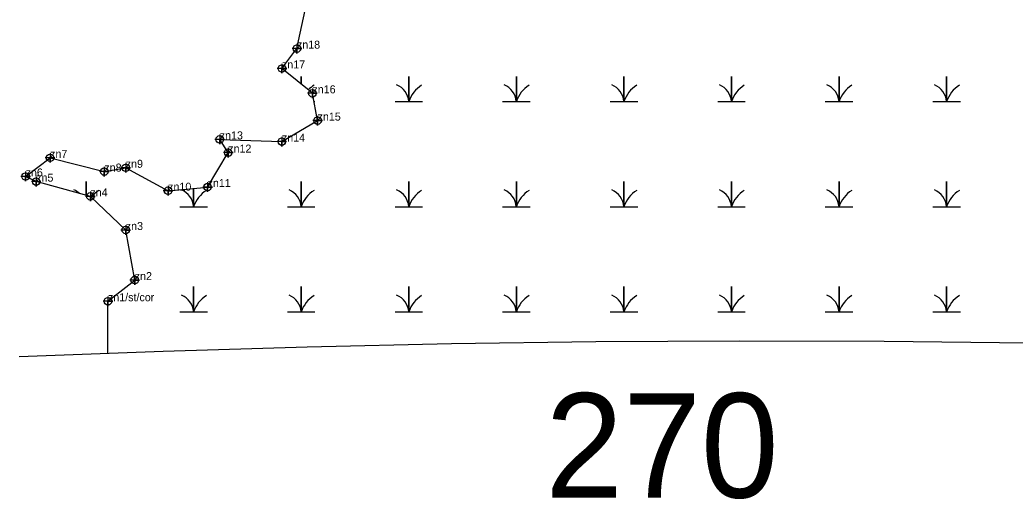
# Model space of a CAD drawing. Extents: x 2071991 to 2268989, y 436479 to 469629.
# Drawn here: x 2230233 to 2230854, y 437821 to 438121 of the extents above; entities that cross this region are included whole.
import ezdxf

# ---------------------------------------------------------------- set-up
doc = ezdxf.new("R2010")
doc.units = 0
for name, color, linetype in [('approx_PSA', 7, 'Continuous'), ('Default', 7, 'Continuous'), ('Exist Environmental Wetland Boundary', 7, 'Continuous'), ('Exist Environmental Wetland Boundary Cogo Comment', 7, 'Continuous'), ('Exist Environmental Wetland Boundary Cogo Point CELL', 7, 'Continuous'), ('Exist Hydro Swamp or Marsh', 7, 'Continuous')]:
    doc.layers.add(name, color=color, linetype=linetype)

msp = doc.modelspace()

# ---------------------------------------------------------------- linework, layer by layer
at = {"layer": 'approx_PSA'}
for p, q in [((2230412.08, 437916.61), (2230322, 437913.9)), ((2230502.18, 437918.58), (2230412.08, 437916.61)), ((2230592.29, 437919.8), (2230502.18, 437918.58)), ((2230682.41, 437920.29), (2230592.29, 437919.8)), ((2230772.53, 437920.03), (2230682.41, 437920.29)), ((2230862.64, 437919.04), (2230772.53, 437920.03)), ((2230322, 437913.9), (2230231.95, 437910.45))]:
    msp.add_line(p, q, dxfattribs=at)
at = {"layer": 'Exist Environmental Wetland Boundary'}
msp.add_lwpolyline([(2230287.44, 437912.58), (2230287.5, 437945.27), (2230304.22, 437958.48), (2230298.64, 437989.83), (2230276.54, 438010.89), (2230242.65, 438020.09), (2230236.05, 438023.33), (2230251.36, 438034.96), (2230285.25, 438026.39), (2230298.62, 438028.75), (2230325.1, 438014.42), (2230349.74, 438016.73), (2230362.65, 438038.26), (2230357.36, 438046.53), (2230396.17, 438045.12), (2230418.47, 438058.27), (2230415.26, 438075.34), (2230396.2, 438090.88), (2230405.57, 438103.3), (2230411.69, 438132.22)], dxfattribs=at)
at = {"layer": 'Exist Environmental Wetland Boundary Cogo Point CELL'}
for points in [[(2230405.57, 438106.3), (2230405.57, 438100.3), (2230405.57, 438103.3), (2230408.57, 438103.3), (2230402.57, 438103.3)], [(2230396.2, 438093.88), (2230396.2, 438087.88), (2230396.2, 438090.88), (2230399.2, 438090.88), (2230393.2, 438090.88)], [(2230415.26, 438078.34), (2230415.26, 438072.34), (2230415.26, 438075.34), (2230418.26, 438075.34), (2230412.26, 438075.34)], [(2230418.47, 438061.27), (2230418.47, 438055.27), (2230418.47, 438058.27), (2230421.47, 438058.27), (2230415.47, 438058.27)], [(2230357.36, 438049.53), (2230357.36, 438043.53), (2230357.36, 438046.53), (2230360.36, 438046.53), (2230354.36, 438046.53)], [(2230396.17, 438048.12), (2230396.17, 438042.12), (2230396.17, 438045.12), (2230399.17, 438045.12), (2230393.17, 438045.12)], [(2230362.65, 438041.26), (2230362.65, 438035.26), (2230362.65, 438038.26), (2230365.65, 438038.26), (2230359.65, 438038.26)], [(2230251.36, 438037.96), (2230251.36, 438031.96), (2230251.36, 438034.96), (2230254.36, 438034.96), (2230248.36, 438034.96)], [(2230285.25, 438029.39), (2230285.25, 438023.39), (2230285.25, 438026.39), (2230288.25, 438026.39), (2230282.25, 438026.39)], [(2230298.62, 438031.75), (2230298.62, 438025.75), (2230298.62, 438028.75), (2230301.62, 438028.75), (2230295.62, 438028.75)], [(2230236.05, 438026.33), (2230236.05, 438020.33), (2230236.05, 438023.33), (2230239.05, 438023.33), (2230233.05, 438023.33)], [(2230242.65, 438023.09), (2230242.65, 438017.09), (2230242.65, 438020.09), (2230245.65, 438020.09), (2230239.65, 438020.09)], [(2230325.1, 438017.42), (2230325.1, 438011.42), (2230325.1, 438014.42), (2230328.1, 438014.42), (2230322.1, 438014.42)], [(2230349.74, 438019.73), (2230349.74, 438013.73), (2230349.74, 438016.73), (2230352.74, 438016.73), (2230346.74, 438016.73)], [(2230276.54, 438013.89), (2230276.54, 438007.89), (2230276.54, 438010.89), (2230279.54, 438010.89), (2230273.54, 438010.89)], [(2230298.64, 437992.83), (2230298.64, 437986.83), (2230298.64, 437989.83), (2230301.64, 437989.83), (2230295.64, 437989.83)], [(2230304.22, 437961.48), (2230304.22, 437955.48), (2230304.22, 437958.48), (2230307.22, 437958.48), (2230301.22, 437958.48)], [(2230287.5, 437948.27), (2230287.5, 437942.27), (2230287.5, 437945.27), (2230290.5, 437945.27), (2230284.5, 437945.27)]]:
    msp.add_lwpolyline(points, dxfattribs=at)
for centre in [(2230405.57, 438103.3), (2230396.2, 438090.88), (2230415.26, 438075.34), (2230418.47, 438058.27), (2230357.36, 438046.53), (2230396.17, 438045.12), (2230251.36, 438034.96), (2230362.65, 438038.26), (2230285.25, 438026.39), (2230298.62, 438028.75), (2230236.05, 438023.33), (2230242.65, 438020.09), (2230325.1, 438014.42), (2230349.74, 438016.73), (2230276.54, 438010.89), (2230298.64, 437989.83), (2230304.22, 437958.48), (2230287.5, 437945.27)]:
    msp.add_circle(centre, 2.34, dxfattribs=at)
at = {"layer": 'Exist Hydro Swamp or Marsh'}
msp.add_line((2230416.23, 438070.18), (2230416.87, 438070.18), dxfattribs=at)
for points in [[(2230408.26, 438081.04), (2230408.26, 438085.96), (2230408.26, 438081.04)], [(2230466.87, 438070.18), (2230475.47, 438070.18), (2230475.47, 438085.96), (2230475.47, 438070.18), (2230484.07, 438070.18)], [(2230534.07, 438070.18), (2230542.67, 438070.18), (2230542.67, 438085.96), (2230542.67, 438070.18), (2230551.27, 438070.18)], [(2230601.27, 438070.18), (2230609.87, 438070.18), (2230609.87, 438085.96), (2230609.87, 438070.18), (2230618.48, 438070.18)], [(2230668.48, 438070.18), (2230677.08, 438070.18), (2230677.08, 438085.96), (2230677.08, 438070.18), (2230685.68, 438070.18)], [(2230735.68, 438070.18), (2230744.28, 438070.18), (2230744.28, 438085.96), (2230744.28, 438070.18), (2230752.88, 438070.18)], [(2230802.88, 438070.18), (2230811.48, 438070.18), (2230811.48, 438085.96), (2230811.48, 438070.18), (2230820.09, 438070.18)], [(2230273.86, 438011.62), (2230273.86, 438020.18), (2230273.86, 438011.62)], [(2230399.66, 438004.4), (2230408.26, 438004.4), (2230408.26, 438020.18), (2230408.26, 438004.4), (2230416.87, 438004.4)], [(2230466.87, 438004.4), (2230475.47, 438004.4), (2230475.47, 438020.18), (2230475.47, 438004.4), (2230484.07, 438004.4)], [(2230534.07, 438004.4), (2230542.67, 438004.4), (2230542.67, 438020.18), (2230542.67, 438004.4), (2230551.27, 438004.4)], [(2230601.27, 438004.4), (2230609.87, 438004.4), (2230609.87, 438020.18), (2230609.87, 438004.4), (2230618.48, 438004.4)], [(2230668.48, 438004.4), (2230677.08, 438004.4), (2230677.08, 438020.18), (2230677.08, 438004.4), (2230685.68, 438004.4)], [(2230735.68, 438004.4), (2230744.28, 438004.4), (2230744.28, 438020.18), (2230744.28, 438004.4), (2230752.88, 438004.4)], [(2230802.88, 438004.4), (2230811.48, 438004.4), (2230811.48, 438020.18), (2230811.48, 438004.4), (2230820.09, 438004.4)], [(2230332.46, 438004.4), (2230341.06, 438004.4), (2230341.06, 438015.92)], [(2230341.06, 438015.92), (2230341.06, 438004.4), (2230349.66, 438004.4)], [(2230332.46, 437938.62), (2230341.06, 437938.62), (2230341.06, 437954.4), (2230341.06, 437938.62), (2230349.66, 437938.62)], [(2230399.66, 437938.62), (2230408.26, 437938.62), (2230408.26, 437954.4), (2230408.26, 437938.62), (2230416.87, 437938.62)], [(2230466.87, 437938.62), (2230475.47, 437938.62), (2230475.47, 437954.4), (2230475.47, 437938.62), (2230484.07, 437938.62)], [(2230534.07, 437938.62), (2230542.67, 437938.62), (2230542.67, 437954.4), (2230542.67, 437938.62), (2230551.27, 437938.62)], [(2230601.27, 437938.62), (2230609.87, 437938.62), (2230609.87, 437954.4), (2230609.87, 437938.62), (2230618.48, 437938.62)], [(2230668.48, 437938.62), (2230677.08, 437938.62), (2230677.08, 437954.4), (2230677.08, 437938.62), (2230685.68, 437938.62)], [(2230735.68, 437938.62), (2230744.28, 437938.62), (2230744.28, 437954.4), (2230744.28, 437938.62), (2230752.88, 437938.62)], [(2230802.88, 437938.62), (2230811.48, 437938.62), (2230811.48, 437954.4), (2230811.48, 437938.62), (2230820.09, 437938.62)]]:
    msp.add_lwpolyline(points, dxfattribs=at)
for centre, radius, start, end in [((2230426.51, 438064.12), 19.22, 122.12745, 136.07469), ((2230463.2, 438069.29), 12.3, 4.14034, 67.53497), ((2230493.71, 438064.12), 19.22, 122.12745, 161.62219), ((2230530.4, 438069.29), 12.3, 4.14034, 67.53497), ((2230560.91, 438064.12), 19.22, 122.12745, 161.62219), ((2230597.61, 438069.29), 12.3, 4.14034, 67.53497), ((2230628.12, 438064.12), 19.22, 122.12745, 161.62219), ((2230664.81, 438069.29), 12.3, 4.14034, 67.53497), ((2230695.32, 438064.12), 19.22, 122.12745, 161.62219), ((2230732.01, 438069.29), 12.3, 4.14034, 67.53497), ((2230762.52, 438064.12), 19.22, 122.12745, 161.62219), ((2230799.22, 438069.29), 12.3, 4.14034, 67.53497), ((2230829.73, 438064.12), 19.22, 122.12745, 161.62219), ((2230261.59, 438003.51), 12.3, 48.65923, 67.53497), ((2230292.1, 437998.34), 19.22, 122.12745, 141.2888), ((2230328.8, 438003.51), 12.3, 4.14034, 67.53497), ((2230359.3, 437998.34), 19.22, 122.12745, 161.62219), ((2230396, 438003.51), 12.3, 4.14034, 67.53497), ((2230426.51, 437998.34), 19.22, 122.12745, 161.62219), ((2230463.2, 438003.51), 12.3, 4.14034, 67.53497), ((2230493.71, 437998.34), 19.22, 122.12745, 161.62219), ((2230530.4, 438003.51), 12.3, 4.14034, 67.53497), ((2230560.91, 437998.34), 19.22, 122.12745, 161.62219), ((2230597.61, 438003.51), 12.3, 4.14034, 67.53497), ((2230628.12, 437998.34), 19.22, 122.12745, 161.62219), ((2230664.81, 438003.51), 12.3, 4.14034, 67.53497), ((2230695.32, 437998.34), 19.22, 122.12745, 161.62219), ((2230732.01, 438003.51), 12.3, 4.14034, 67.53497), ((2230762.52, 437998.34), 19.22, 122.12745, 161.62219), ((2230799.22, 438003.51), 12.3, 4.14034, 67.53497), ((2230829.73, 437998.34), 19.22, 122.12745, 161.62219), ((2230328.8, 437937.73), 12.3, 4.14034, 67.53497), ((2230359.3, 437932.56), 19.22, 122.12745, 161.62219), ((2230396, 437937.73), 12.3, 4.14034, 67.53497), ((2230426.51, 437932.56), 19.22, 122.12745, 161.62219), ((2230463.2, 437937.73), 12.3, 4.14034, 67.53497), ((2230493.71, 437932.56), 19.22, 122.12745, 161.62219), ((2230530.4, 437937.73), 12.3, 4.14034, 67.53497), ((2230560.91, 437932.56), 19.22, 122.12745, 161.62219), ((2230597.61, 437937.73), 12.3, 4.14034, 67.53497), ((2230628.12, 437932.56), 19.22, 122.12745, 161.62219), ((2230664.81, 437937.73), 12.3, 4.14034, 67.53497), ((2230695.32, 437932.56), 19.22, 122.12745, 161.62219), ((2230732.01, 437937.73), 12.3, 4.14034, 67.53497), ((2230762.52, 437932.56), 19.22, 122.12745, 161.62219), ((2230799.22, 437937.73), 12.3, 4.14034, 67.53497), ((2230829.73, 437932.56), 19.22, 122.12745, 161.62219)]:
    msp.add_arc(centre, radius, start, end, dxfattribs=at)

# ---------------------------------------------------------------- texts
at = {"layer": 'Default'}
msp.add_text('270', height=65.34, dxfattribs=at).set_placement((2230560.8, 437822.39))
at = {"layer": 'Exist Environmental Wetland Boundary Cogo Comment'}
for s, p in [('zn18', (2230405.57, 438103.3)), ('zn17', (2230396.2, 438090.88)), ('zn16', (2230415.26, 438075.34)), ('zn15', (2230418.47, 438058.27)), ('zn13', (2230357.36, 438046.53)), ('zn14', (2230396.17, 438045.12)), ('zn12', (2230362.65, 438038.26)), ('zn7', (2230251.36, 438034.96)), ('zn8', (2230285.25, 438026.39)), ('zn9', (2230298.62, 438028.75)), ('zn6', (2230236.05, 438023.33)), ('zn5', (2230242.65, 438020.09)), ('zn10', (2230325.1, 438014.42)), ('zn11', (2230349.74, 438016.73)), ('zn4', (2230276.54, 438010.89)), ('zn3', (2230298.64, 437989.83)), ('zn2', (2230304.22, 437958.48)), ('zn1/st/cor', (2230287.5, 437945.27))]:
    msp.add_text(s, height=5, dxfattribs=at).set_placement(p)

doc.saveas('drawing.dxf')
